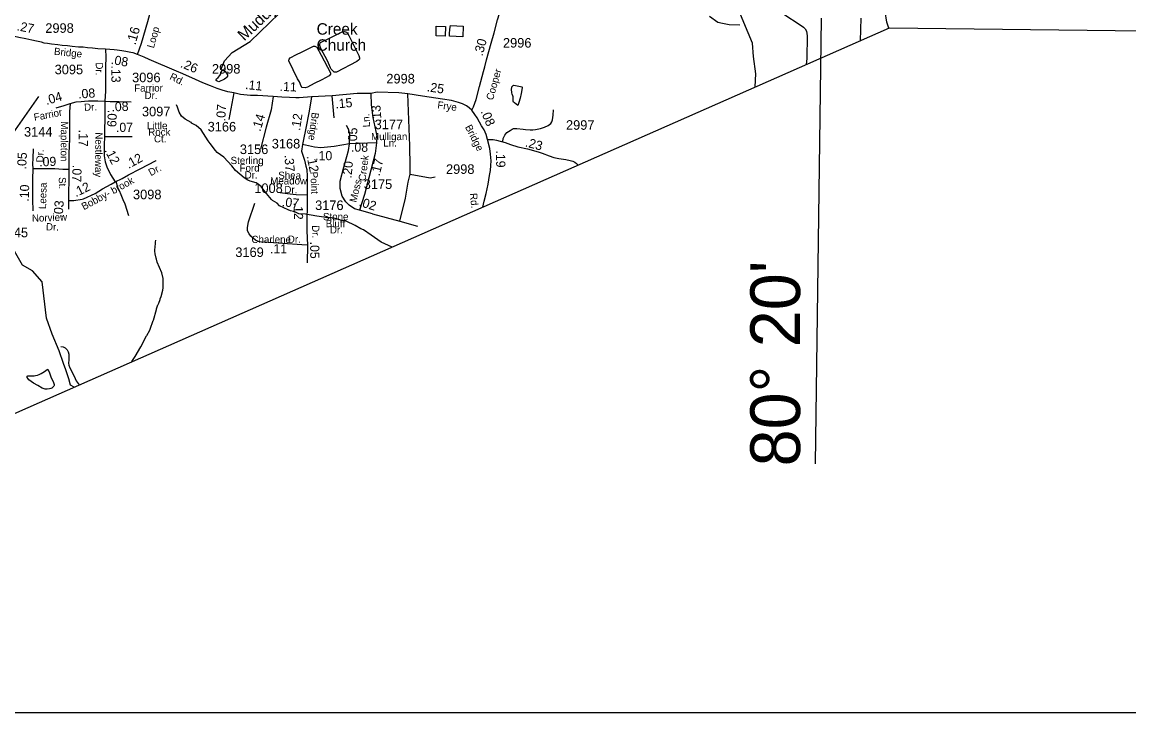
# Model space of a CAD drawing. Extents: x 1547597 to 1699558, y 810033 to 920809.
# Drawn here: x 1595166 to 1609618, y 811336 to 820357 of the extents above; entities that cross this region are included whole.
import ezdxf

# ---------------------------------------------------------------- set-up
doc = ezdxf.new("R2010")
doc.units = 0
for name, color, linetype in [('Exist Boundary Political CountyLine', 7, 'Continuous'), ('Exist Cultural Church with Cemetery Label', 7, 'Continuous'), ('Exist Hydrographic Creek Single Shore', 7, 'Continuous'), ('Exist Hydrographic Creek Single Shore Label', 7, 'Continuous'), ('Exist Hydrographic Misc Water Feature', 7, 'Continuous'), ('Exist Road Non-System Type 51', 7, 'Continuous'), ('Exist Road Secondary Mileage Hundredths English Label', 7, 'Continuous'), ('Exist Road Secondary Type 41 Attributed', 7, 'Continuous'), ('Exist Road Secondary Type 51 Attributed', 7, 'Continuous'), ('Exist Road Secondary Type 51 Label', 7, 'Continuous'), ('Exist Road Secondary Type 51 Number Label', 7, 'Continuous'), ('Map Preparation Inset Cut Line', 7, 'Continuous'), ('Map Preparation Longitude Latitude Label', 7, 'Continuous'), ('Map Preparation Longitude Latitude Lines', 7, 'Continuous')]:
    doc.layers.add(name, color=color, linetype=linetype)

msp = doc.modelspace()

# ---------------------------------------------------------------- linework, layer by layer
at = {"layer": 'Exist Boundary Political CountyLine'}
msp.add_lwpolyline([(1587438, 811881), (1587926, 812095), (1588566, 812375), (1589264, 812687), (1590110, 813060), (1590806, 813364), (1591554, 813702), (1592251, 814009), (1592815, 814258), (1593255, 814450), (1606493, 820282), (1613861, 820194)], dxfattribs=at)
at = {"layer": 'Exist Hydrographic Creek Single Shore'}
for points in [[(1597763, 819736), (1597807, 819853), (1597908, 819960), (1598143, 820106), (1598650, 820591), (1598862, 820882), (1598996, 820945), (1599147, 820942), (1599354, 820840), (1599989, 820965), (1600165, 821056), (1600335, 821296), (1600612, 821441), (1600840, 821665)], [(1604739, 819510), (1604747, 819681), (1604715, 819908), (1604704, 820081), (1604589, 820352), (1604518, 820531), (1604372, 820858), (1604358, 820941), (1604314, 821035), (1604218, 821128), (1603953, 821299), (1603843, 821480), (1603749, 821581)], [(1606483, 820278), (1606458, 820355), (1606434, 820496), (1606374, 820690), (1606353, 820821), (1606296, 821005), (1606292, 821069), (1606284, 821131), (1606274, 821173), (1606245, 821218), (1606177, 821266), (1606161, 821442)], [(1595846, 815591), (1595798, 815614), (1595776, 815699), (1595738, 815817), (1595707, 815899), (1595650, 816063), (1595558, 816281), (1595486, 816490), (1595426, 816967), (1595303, 817111), (1595170, 817185), (1595048, 817398), (1595049, 817431), (1594901, 817647), (1594829, 817832), (1594798, 818043), (1594860, 818341), (1594903, 818425), (1594948, 818700), (1595017, 818863), (1595383, 819384)]]:
    msp.add_lwpolyline(points, dxfattribs=at)
at = {"layer": 'Exist Hydrographic Misc Water Feature'}
for points in [[(1604538, 820317), (1604399, 820322), (1604311, 820341), (1604251, 820350), (1604143, 820432)], [(1600694, 820301), (1600691, 820173), (1600572, 820178), (1600573, 820303), (1600694, 820301)], [(1600758, 820315), (1600927, 820304), (1600920, 820167), (1600747, 820175), (1600746, 820205), (1600751, 820267), (1600758, 820315)], [(1599189, 820154), (1599346, 820232), (1599377, 820235), (1599400, 820227), (1599414, 820211), (1599432, 820181), (1599561, 819922), (1599571, 819890), (1599571, 819874), (1599560, 819859), (1599538, 819843), (1599272, 819704), (1599240, 819704), (1599232, 819711), (1599202, 819743), (1599193, 819761), (1599154, 819850), (1599067, 820011), (1599053, 820051), (1599054, 820075), (1599064, 820091), (1599189, 820154)], [(1598823, 819502), (1598811, 819520), (1598786, 819577), (1598762, 819617), (1598650, 819851), (1598655, 819875), (1598667, 819890), (1598747, 819933), (1598815, 819965), (1598973, 820043), (1598989, 820045), (1599013, 820032), (1599071, 819927), (1599192, 819693), (1599191, 819677), (1599177, 819656), (1599078, 819603), (1598981, 819557), (1598892, 819509), (1598860, 819499), (1598823, 819502)], [(1597777, 819731), (1597792, 819730), (1597800, 819726), (1597816, 819714), (1597837, 819689), (1597847, 819669), (1597847, 819653), (1597838, 819637), (1597826, 819624), (1597810, 819614), (1597737, 819579), (1597714, 819584), (1597700, 819596), (1597698, 819604), (1597704, 819616), (1597728, 819635), (1597747, 819659), (1597759, 819683), (1597759, 819691), (1597777, 819731)], [(1601676, 819518), (1601690, 819513), (1601694, 819509), (1601694, 819501), (1601682, 819426), (1601669, 819366), (1601653, 819308), (1601638, 819270), (1601595, 819301), (1601584, 819312), (1601579, 819323), (1601577, 819338), (1601577, 819382), (1601574, 819395), (1601565, 819418), (1601561, 819434), (1601558, 819481), (1601560, 819505), (1601562, 819513), (1601573, 819527), (1601577, 819530), (1601585, 819532), (1601676, 819518)], [(1599996, 817420), (1599950, 817442), (1599856, 817485), (1599724, 817574), (1599622, 817643), (1599590, 817656), (1599515, 817701), (1599399, 817759), (1599332, 817768), (1599316, 817777), (1599236, 817798), (1599220, 817798), (1599206, 817803), (1599144, 817802), (1599104, 817812), (1599016, 817822), (1598865, 817849), (1598781, 817854), (1598729, 817879), (1598721, 817877), (1598709, 817883), (1598669, 817892), (1598638, 817905), (1598527, 817957), (1598497, 817991), (1598436, 818028), (1598422, 818040), (1598381, 818093), (1598334, 818146), (1598287, 818211), (1598224, 818260), (1598144, 818281), (1598112, 818294), (1598065, 818323), (1597954, 818420), (1597904, 818482), (1597801, 818595), (1597714, 818655), (1597690, 818679), (1597622, 818774), (1597595, 818806), (1597504, 818951), (1597440, 819005), (1597380, 819038), (1597378, 819044), (1597373, 819048), (1597297, 819088), (1597246, 819130), (1597219, 819181), (1597196, 819245), (1597180, 819277)], [(1596599, 815923), (1596642, 815990), (1596716, 816117), (1596790, 816259), (1596798, 816267), (1596813, 816299), (1596821, 816307), (1596840, 816346), (1596876, 816462), (1596882, 816465), (1596920, 816605), (1596920, 816612), (1596937, 816664), (1596943, 816668), (1596953, 816688), (1596970, 816735), (1596970, 816743), (1596983, 816775), (1597004, 816855), (1597009, 816887), (1597008, 817011), (1596992, 817083), (1596930, 817224), (1596923, 817260), (1596915, 817276), (1596904, 817330), (1596901, 817366), (1596902, 817436), (1596906, 817452), (1596906, 817484), (1596911, 817508)], [(1595507, 815816), (1595522, 815775), (1595543, 815723), (1595574, 815649), (1595583, 815623), (1595583, 815612), (1595581, 815604), (1595566, 815588), (1595553, 815578), (1595539, 815572), (1595522, 815568), (1595494, 815564), (1595469, 815564), (1595454, 815566), (1595428, 815578), (1595373, 815610), (1595316, 815641), (1595283, 815664), (1595256, 815685), (1595244, 815698), (1595233, 815715), (1595231, 815724), (1595233, 815732), (1595239, 815737), (1595251, 815739), (1595323, 815738), (1595343, 815740), (1595365, 815745), (1595388, 815755), (1595417, 815769), (1595459, 815794), (1595495, 815822), (1595501, 815823), (1595504, 815822), (1595507, 815816)]]:
    msp.add_lwpolyline(points, dxfattribs=at)
at = {"layer": 'Exist Road Non-System Type 51'}
for p, q in [((1599240, 819108), (1599216, 819394)), ((1596915, 818552), (1596915, 818552)), ((1599742, 817854), (1600098, 817758)), ((1600098, 817758), (1600331, 817692))]:
    msp.add_line(p, q, dxfattribs=at)
for points in [[(1605100, 820470), (1605337, 820312), (1605368, 820290), (1605391, 820269), (1605410, 820240), (1605415, 820179), (1605411, 819884), (1605404, 819803)], [(1606118, 820408), (1606111, 820114)], [(1600232, 818372), (1600234, 818474), (1600227, 818742), (1600202, 819420)], [(1601444, 818797), (1601447, 818839), (1601471, 818880), (1601496, 818915), (1601540, 818942), (1601563, 818958), (1601583, 818966), (1601625, 818968), (1601707, 818960), (1601737, 818956), (1601802, 818950), (1601837, 818952), (1601869, 818954), (1601934, 818969), (1601986, 818987), (1602033, 819008), (1602068, 819032), (1602084, 819056), (1602091, 819082), (1602101, 819144), (1602106, 819212)], [(1596392, 818278), (1596412, 818203), (1596435, 818159), (1596454, 818104), (1596481, 818042), (1596509, 817984), (1596554, 817830)], [(1600098, 817758), (1600171, 818056), (1600207, 818265), (1600232, 818372)], [(1600232, 818372), (1600494, 818324), (1600560, 818338)], [(1598309, 817479), (1598252, 817492), (1598212, 817510), (1598186, 817532), (1598151, 817563), (1598133, 817594), (1598111, 817633), (1598111, 817677), (1598124, 817748), (1598203, 817994)], [(1595670, 816121), (1595701, 816115), (1595730, 816104), (1595755, 816079), (1595769, 816051), (1595778, 816021), (1595776, 815990), (1595775, 815947), (1595771, 815903), (1595775, 815879), (1595790, 815841), (1595844, 815734), (1595873, 815674), (1595909, 815619)]]:
    msp.add_lwpolyline(points, dxfattribs=at)
at = {"layer": 'Exist Road Secondary Type 41 Attributed'}
msp.add_lwpolyline([(1601245, 818826), (1601318, 818823), (1601362, 818817), (1601472, 818784), (1601544, 818759), (1601640, 818730), (1601764, 818701), (1601903, 818663), (1601957, 818644), (1602047, 818610), (1602109, 818590), (1602175, 818575), (1602265, 818564), (1602322, 818552), (1602359, 818541), (1602385, 818530), (1602405, 818512), (1602427, 818491)], dxfattribs=at)
at = {"layer": 'Exist Road Secondary Type 51 Attributed'}
for p, q in [((1597932, 819432), (1597866, 819087)), ((1599795, 818781), (1599443, 818766)), ((1599742, 817854), (1599573, 817900)), ((1598891, 817446), (1598890, 817214))]:
    msp.add_line(p, q, dxfattribs=at)
for points in [[(1596671, 819936), (1596726, 820083), (1596807, 820367), (1596856, 820541), (1596907, 820726)], [(1601040, 819209), (1601059, 819252), (1601094, 819347), (1601138, 819517), (1601191, 819713), (1601208, 819772), (1601232, 819864), (1601292, 820084), (1601331, 820219), (1601374, 820387), (1601398, 820469), (1601429, 820578), (1601467, 820694), (1601498, 820733)], [(1596257, 820002), (1596154, 820009), (1596084, 820015), (1596022, 820021), (1595965, 820028), (1595901, 820030), (1595821, 820039), (1595757, 820046), (1595691, 820053), (1595633, 820059), (1595552, 820069), (1595498, 820077), (1595454, 820084), (1595418, 820096), (1595353, 820108), (1595293, 820122), (1595215, 820137), (1595123, 820158), (1595027, 820180), (1594941, 820199), (1594871, 820216), (1594799, 820231), (1594726, 820249)], [(1596257, 820002), (1596259, 819900), (1596257, 819775), (1596253, 819596), (1596254, 819457), (1596248, 819323)], [(1596671, 819936), (1596618, 819955), (1596584, 819962), (1596520, 819974), (1596468, 819983), (1596408, 819990), (1596367, 819994), (1596257, 820002)], [(1597932, 819432), (1597853, 819447), (1597778, 819469), (1597715, 819491), (1597627, 819527), (1597527, 819566), (1597428, 819607), (1597266, 819681), (1597181, 819717), (1596823, 819870), (1596760, 819899), (1596671, 819936)], [(1598446, 819386), (1598239, 819397), (1598148, 819399), (1598017, 819414), (1597932, 819432)], [(1599719, 819427), (1599543, 819425), (1599216, 819394), (1598947, 819380)], [(1601040, 819209), (1601005, 819239), (1600969, 819265), (1600918, 819290), (1600865, 819309), (1600773, 819332), (1600657, 819352), (1600393, 819392), (1600202, 819420), (1600084, 819432), (1599802, 819441), (1599719, 819427)], [(1599719, 819427), (1599722, 819277), (1599747, 819113), (1599797, 818868), (1599795, 818781)], [(1595610, 819239), (1595716, 819269), (1595794, 819293)], [(1595794, 819293), (1595787, 819187), (1595785, 819051), (1595786, 818828), (1595776, 818644), (1595777, 818433)], [(1595794, 819293), (1595871, 819315), (1595936, 819321), (1595980, 819324), (1596033, 819327), (1596154, 819327), (1596248, 819323)], [(1596248, 819323), (1596247, 819193), (1596248, 819066), (1596243, 818978), (1596240, 818863)], [(1596248, 819323), (1596317, 819321), (1596429, 819322), (1596588, 819318)], [(1598446, 819386), (1598419, 819211), (1598352, 818984), (1598277, 818700)], [(1598947, 819380), (1598783, 819370), (1598742, 819370), (1598659, 819371), (1598559, 819376), (1598446, 819386)], [(1598947, 819380), (1598915, 819196), (1598867, 818949), (1598841, 818824), (1598828, 818757)], [(1601245, 818826), (1601225, 818888), (1601198, 818952), (1601164, 819004), (1601138, 819052), (1601107, 819105), (1601078, 819151), (1601040, 819209)], [(1599443, 818766), (1599445, 818892), (1599433, 818949), (1599401, 819005)], [(1596240, 818863), (1596239, 818749), (1596236, 818698), (1596237, 818613), (1596241, 818585), (1596250, 818533), (1596274, 818466), (1596322, 818368), (1596382, 818273)], [(1596240, 818863), (1596410, 818862), (1596490, 818863), (1596602, 818863)], [(1601182, 817942), (1601200, 818020), (1601224, 818117), (1601250, 818243), (1601271, 818356), (1601283, 818418), (1601287, 818486), (1601290, 818547), (1601284, 818634), (1601273, 818706), (1601245, 818826)], [(1595309, 818703), (1595306, 818576), (1595303, 818508), (1595306, 818443)], [(1598828, 818757), (1598814, 818672), (1598853, 818553), (1598873, 818476), (1598882, 818433), (1598890, 818347), (1598889, 818095)], [(1599443, 818766), (1599241, 818734), (1599066, 818717), (1598984, 818723), (1598828, 818757)], [(1599573, 817900), (1599508, 817920), (1599437, 817965), (1599391, 818011), (1599347, 818083), (1599318, 818185), (1599321, 818281), (1599369, 818461), (1599407, 818600), (1599429, 818680), (1599443, 818766)], [(1599795, 818781), (1599778, 818640), (1599635, 818104), (1599573, 817900)], [(1596382, 818273), (1596471, 818314), (1596557, 818361), (1596706, 818440), (1596915, 818552)], [(1595306, 818443), (1595303, 818308), (1595303, 818039), (1595306, 817891)], [(1595777, 818433), (1595699, 818434), (1595593, 818440), (1595442, 818443), (1595306, 818443)], [(1595777, 818433), (1595777, 818309), (1595773, 818112), (1595773, 818026)], [(1595773, 818026), (1595843, 818026), (1595950, 818047), (1595966, 818051), (1596120, 818117), (1596214, 818178), (1596329, 818241), (1596382, 818273)], [(1598889, 818095), (1598746, 818103), (1598668, 818112), (1598502, 818134)], [(1598889, 818095), (1598885, 817633), (1598891, 817446)], [(1595773, 818026), (1595773, 817975), (1595772, 817916)], [(1598891, 817446), (1598817, 817447), (1598324, 817483)]]:
    msp.add_lwpolyline(points, dxfattribs=at)
at = {"layer": 'Map Preparation Inset Cut Line'}
msp.add_lwpolyline([(1575503, 831307), (1641329, 831307), (1641329, 811336), (1575503, 811336)], close=True, dxfattribs=at)
at = {"layer": 'Map Preparation Longitude Latitude Lines'}
msp.add_line((1605528, 814587), (1605606, 820407), dxfattribs=at)

# ---------------------------------------------------------------- texts
at = {"layer": 'Exist Cultural Church with Cemetery Label'}
for s, p in [('Creek ', (1599012, 820193)), ('Church', (1599012, 819983))]:
    msp.add_text(s, height=150, dxfattribs=at).set_placement(p)
at = {"layer": 'Exist Hydrographic Creek Single Shore Label'}
msp.add_text('Muddy', height=150, rotation=43.7512, dxfattribs=at).set_placement((1598067, 820104))
at = {"layer": 'Exist Road Secondary Mileage Hundredths English Label'}
for s, height, rotation, p in [('.27', 120, 349.2329, (1595091, 820251)), ('.16', 125, 74.187, (1596645, 820052)), ('.30', 120, 75.1053, (1601178, 819907)), ('.08', 120, 350.2095, (1596320, 819812)), ('.26', 120, 337.5725, (1597224, 819773)), ('.13', 120, 270.2428, (1596331, 819790)), ('.11', 120, 354.2912, (1598075, 819484)), ('.11', 120, 357.7568, (1598527, 819459)), ('.25', 120, 352.0331, (1600446, 819454)), ('.04', 120, 15.9421, (1595485, 819275)), ('.08', 120, 4.1511, (1595902, 819358)), ('.08', 120, 2.3231, (1596335, 819190)), ('.07', 120, 86.2173, (1597818, 819059)), ('.15', 120, 5.3632, (1599261, 819228)), ('.13', 120, 94.1, (1599860, 819054)), ('.09', 120, 267.2649, (1596286, 819213)), ('.14', 120, 72.7959, (1598276, 818922)), ('.12', 120, 81.2218, (1598794, 818935)), ('.08', 120, 293.0892, (1601150, 819190)), ('.07', 120, 0.6997, (1596392, 818922)), ('.05', 120, 88.9043, (1599539, 818756)), ('.17', 120, 270.2446, (1595906, 818952)), ('.23', 120, 345.3241, (1601728, 818735)), ('.12', 120, 297.6037, (1596239, 818683)), ('.10', 120, 0.2865, (1598993, 818553)), ('.08', 120, 359.1863, (1599460, 818666)), ('.19', 120, 270.4827, (1601355, 818680)), ('.05', 120, 87.2994, (1595219, 818431)), ('.09', 120, 2.0192, (1595391, 818472)), ('.12', 120, 28.8634, (1596557, 818439)), ('.37', 120, 274.0792, (1598591, 818621)), ('.12', 120, 281.7807, (1598880, 818605)), ('.20', 120, 84.3649, (1599466, 818314)), ('.17', 120, 76.4319, (1599833, 818341)), ('.07', 120, 267.6386, (1595826, 818494)), ('.10', 120, 88.3458, (1595253, 818011)), ('.12', 120, 25.9485, (1595868, 818070)), ('.03', 120, 85.2341, (1595694, 817801)), ('.07', 120, 353.6554, (1598554, 817954)), ('.12', 120, 270.5351, (1598713, 817999)), ('.02', 120, 342.7818, (1599556, 817959)), ('.11', 120, 359.9805, (1598403, 817337)), ('.05', 120, 270.4827, (1598927, 817490))]:
    msp.add_text(s, height=height, rotation=rotation, dxfattribs=at).set_placement(p)
at = {"layer": 'Exist Road Secondary Type 51 Label'}
for s, rotation, p in [('Loop', 74.4096, (1596886, 820010)), ('Bridge', 354.3977, (1595579, 819930)), ('Dr.', 270.1736, (1596128, 819831)), ('Rd.', 333.4605, (1597083, 819614)), ('Cooper', 74.3561, (1601314, 819330)), ('Farrior', 0.482, (1596630, 819448)), ('Dr.', 0.124, (1596765, 819353)), ('Dr.', 1.9729, (1595977, 819198)), ('Frye', 352.1012, (1600584, 819231)), ('Farrior', 10.9247, (1595328, 819066)), ('Bridge', 262.8427, (1598949, 819182)), ('Ln.', 94.1, (1599711, 818987)), ('Mapleton', 269.5658, (1595673, 819061)), ('Bridge', 296.8633, (1600947, 818988)), ('Nestleway', 269.3256, (1596123, 818918)), ('Dr.', 89.2043, (1595446, 818525)), ('Creek', 82.7734, (1599651, 818277)), ('Dr.', 28.345, (1596847, 818344)), ('Shea', 359.9805, (1598511, 818309)), ('Point', 272.2377, (1598931, 818402)), ('Leesa', 88.6663, (1595479, 817915)), ('St.', 271.456, (1595644, 818332)), ('Bobby- brook', 28.5089, (1595973, 817899)), ('Meadow', 359.9805, (1598406, 818237)), ('Moss', 76.4319, (1599530, 817996)), ('Dr.', 359.9805, (1598591, 818123)), ('Rd.', 275.6947, (1601012, 818120)), ('Norview', 2.0192, (1595296, 817749)), ('Dr.', 358.7857, (1595477, 817638)), ('Dr.', 270.8624, (1598952, 817705))]:
    msp.add_text(s, height=95, rotation=rotation, dxfattribs=at).set_placement(p)
for s, p in [('Little', (1596795, 818959)), ('Rock', (1596813, 818875)), ('Ct.', (1596888, 818787)), ('Mulligan', (1599723, 818816)), ('Ln.', (1599882, 818732)), ('Sterling', (1597889, 818503)), ('Ford', (1598006, 818406)), ('Dr.', (1598072, 818314)), ('Stone', (1599095, 817770)), ('Bluff', (1599131, 817679)), ('Dr.', (1599185, 817597)), ('Charlene', (1598161, 817472)), ('Dr.', (1598636, 817475))]:
    msp.add_text(s, height=95, dxfattribs=at).set_placement(p)
at = {"layer": 'Exist Road Secondary Type 51 Number Label'}
for s, p in [('2998', (1595469, 820217)), ('2996', (1601445, 820024)), ('3095', (1595591, 819676)), ('3096', (1596602, 819572)), ('2998', (1597645, 819685)), ('2998', (1599922, 819556)), ('3097', (1596731, 819127)), ('3144', (1595191, 818862)), ('3166', (1597589, 818929)), ('3177', (1599769, 818959)), ('2997', (1602268, 818951)), ('3168', (1598426, 818707)), ('3156', (1598009, 818634)), ('2998', (1600701, 818375)), ('1008', (1598198, 818126)), ('3175', (1599627, 818178)), ('3098', (1596614, 818044)), ('3176', (1598992, 817903)), ('3145', (1594872, 817547)), ('3169', (1597950, 817290))]:
    msp.add_text(s, height=125, dxfattribs=at).set_placement(p)
at = {"layer": 'Map Preparation Longitude Latitude Label'}
msp.add_text("80° 20'", height=650, rotation=90, dxfattribs=at).set_placement((1605325, 814555))

doc.saveas('drawing.dxf')
